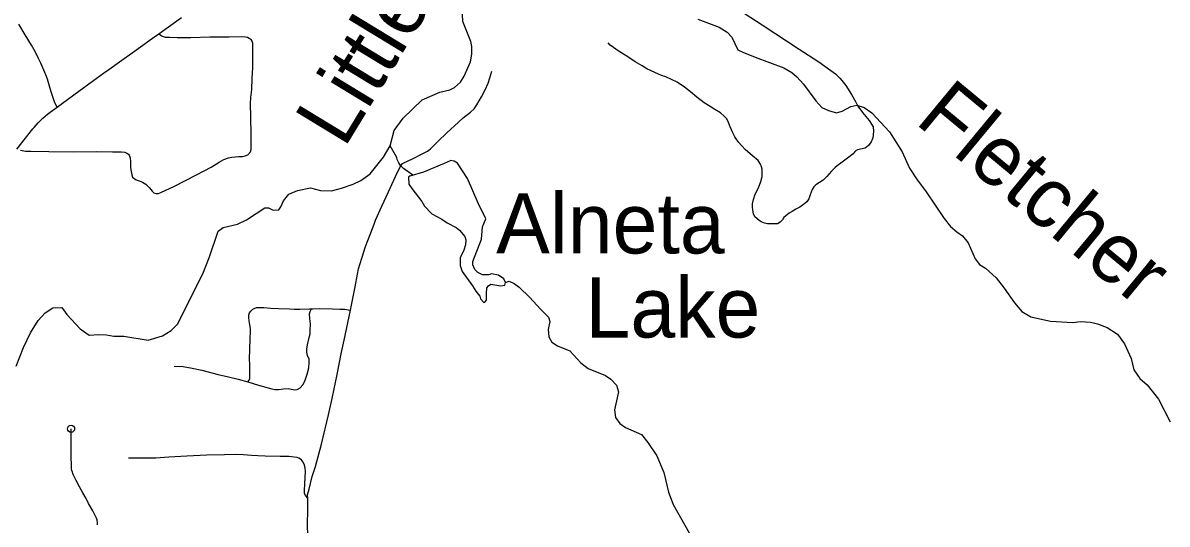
# Model space of a CAD drawing. Extents: x -19 to 366, y -4 to 359.
# Drawn here: x 139.407 to 140.926, y 193.112 to 193.777 of the extents above; entities that cross this region are included whole.
import ezdxf

# ---------------------------------------------------------------- set-up
doc = ezdxf.new("R2010")
doc.units = 0
for name, color, linetype in [('R_ROW', 7, 'Continuous'), ('R_ROW Annot', 7, 'Continuous'), ('R_Temp Easement', 7, 'Continuous'), ('Sheet Fence', 7, 'Continuous')]:
    doc.layers.add(name, color=color, linetype=linetype)

msp = doc.modelspace()

# ---------------------------------------------------------------- linework, layer by layer
at = {"layer": 'R_ROW'}
for points in [[(139.5877, 193.7626), (139.5975, 193.7697), (139.6178, 193.7843)], [(140.3569, 193.7949), (140.3883, 193.7743), (140.4375, 193.7422), (140.4635, 193.7253), (140.4797, 193.7138), (140.4856, 193.7096), (140.4916, 193.7038), (140.4944, 193.7004), (140.4995, 193.6941), (140.5071, 193.6818), (140.5128, 193.672), (140.5155, 193.6663), (140.5218, 193.658), (140.5304, 193.6474), (140.5358, 193.6392), (140.5364, 193.6327), (140.5353, 193.6246), (140.5331, 193.6192)], [(139.4529, 193.6652), (139.4498, 193.6708), (139.4456, 193.684), (139.4438, 193.6901), (139.4419, 193.6962), (139.4399, 193.7022), (139.4377, 193.7082), (139.4365, 193.7113), (139.4339, 193.7175), (139.4312, 193.7236), (139.4283, 193.7296), (139.4253, 193.7356), (139.4222, 193.7415), (139.419, 193.7473), (139.4106, 193.7614), (139.4022, 193.7753)], [(139.5146, 193.7102), (139.5213, 193.715), (139.5358, 193.7255), (139.5555, 193.7396), (139.5795, 193.7567), (139.5877, 193.7626)], [(139.7098, 193.6781), (139.7111, 193.6887), (139.7118, 193.7032), (139.7126, 193.7177), (139.7126, 193.7351), (139.7125, 193.7502), (139.7117, 193.7528), (139.7102, 193.755), (139.7079, 193.7565), (139.7056, 193.7577), (139.7027, 193.7583), (139.6979, 193.7586), (139.6814, 193.7582), (139.6554, 193.758), (139.6303, 193.7573), (139.6122, 193.7574), (139.6019, 193.7575), (139.5968, 193.7577), (139.5916, 193.7593), (139.5877, 193.7626)], [(139.4529, 193.6652), (139.4598, 193.6703), (139.4819, 193.6865), (139.5, 193.6996), (139.5146, 193.7102)], [(139.8423, 193.3957), (139.8483, 193.4266), (139.8513, 193.4436), (139.853, 193.4504), (139.8571, 193.4649), (139.8619, 193.4801), (139.8651, 193.4883), (139.8692, 193.4982), (139.8735, 193.51), (139.8754, 193.5152), (139.8838, 193.5337), (139.8926, 193.5526), (139.9043, 193.5781), (139.909, 193.5872), (139.9112, 193.5902), (139.9137, 193.5916), (139.9178, 193.5934), (139.9261, 193.5974), (139.9364, 193.6026), (139.9445, 193.6067), (139.9482, 193.61), (139.9583, 193.6196), (139.9702, 193.631), (139.9857, 193.6453), (139.9919, 193.6512), (140.0013, 193.6585), (140.0063, 193.6628), (140.0098, 193.6682), (140.016, 193.679), (140.0208, 193.6883), (140.0249, 193.6972), (140.0272, 193.7042), (140.0297, 193.7128)], [(139.3994, 193.6096), (139.4208, 193.6364), (139.4224, 193.6383), (139.4251, 193.6415), (139.4279, 193.6446), (139.4308, 193.6476), (139.4339, 193.6505), (139.437, 193.6532), (139.4402, 193.6559), (139.4435, 193.6584), (139.4529, 193.6652)], [(139.8179, 193.2783), (139.8245, 193.3103), (139.83, 193.3377), (139.835, 193.3621), (139.8423, 193.3957)], [(139.7854, 193.1463), (139.7853, 193.1507), (139.7872, 193.1581), (139.7915, 193.175), (139.7959, 193.1882), (139.8036, 193.2178), (139.8129, 193.2567), (139.8179, 193.2783)], [(139.5064, 193.1108), (139.5065, 193.1139), (139.5061, 193.117), (139.5052, 193.1196), (139.5001, 193.1294), (139.4945, 193.1393), (139.4912, 193.1458), (139.4871, 193.1534), (139.4824, 193.1614), (139.4781, 193.1697), (139.4746, 193.1768), (139.4738, 193.1788), (139.4731, 193.1809), (139.4725, 193.183), (139.4721, 193.1852), (139.4719, 193.1874), (139.4718, 193.1896), (139.4716, 193.2015), (139.4716, 193.2133), (139.4716, 193.2223), (139.4716, 193.2264), (139.4716, 193.23), (139.4714, 193.2383)], [(139.7854, 193.1463), (139.7825, 193.1498), (139.7812, 193.1527), (139.7811, 193.1561), (139.7814, 193.1657), (139.7823, 193.1811), (139.7819, 193.1864), (139.7808, 193.1912), (139.7791, 193.1946), (139.7771, 193.197), (139.7738, 193.1991), (139.7714, 193.2), (139.7674, 193.2007), (139.7602, 193.2014), (139.749, 193.2014), (139.729, 193.2019), (139.7193, 193.2023), (139.7109, 193.2029), (139.7, 193.2038), (139.6899, 193.204), (139.675, 193.2036), (139.6516, 193.2031), (139.625, 193.202), (139.6013, 193.2006), (139.5838, 193.1994), (139.5749, 193.1992), (139.5686, 193.1992), (139.5594, 193.1995), (139.5476, 193.1994)], [(139.7854, 193.0942), (139.7852, 193.1136), (139.7854, 193.1286), (139.7854, 193.1463)]]:
    msp.add_lwpolyline(points, dxfattribs=at)
msp.add_circle((139.4714, 193.2383), 0.00473, dxfattribs=at)
at = {"layer": 'R_ROW Annot'}
for points in [[(140.3462, 193.639), (140.3438, 193.6449), (140.3414, 193.6495), (140.3381, 193.6533), (140.3331, 193.6575), (140.3256, 193.6622), (140.3194, 193.666), (140.3116, 193.6711), (140.3019, 193.6786), (140.2935, 193.6855), (140.2853, 193.6919), (140.2756, 193.6985), (140.2682, 193.7021), (140.2605, 193.7054), (140.2547, 193.7074), (140.2459, 193.7113), (140.2354, 193.7162), (140.2291, 193.7201), (140.22, 193.7253), (140.21, 193.7319), (140.1988, 193.7391), (140.1866, 193.7476), (140.1839, 193.7506)], [(139.4044, 193.6082), (139.411, 193.607), (139.4181, 193.607), (139.4418, 193.6063), (139.4749, 193.6061), (139.5046, 193.6062), (139.5264, 193.6061), (139.5385, 193.6059), (139.5427, 193.6053), (139.5452, 193.6043), (139.5475, 193.6026), (139.5489, 193.6006), (139.5497, 193.5978), (139.5504, 193.5925), (139.5502, 193.5862), (139.5506, 193.5819), (139.5519, 193.5753), (139.5529, 193.5721), (139.5577, 193.5688), (139.5619, 193.5676), (139.5663, 193.5658), (139.5708, 193.5628), (139.5755, 193.5583), (139.5789, 193.5535), (139.5812, 193.5513), (139.5842, 193.5505), (139.5872, 193.5506), (139.5915, 193.5525), (139.6076, 193.5601), (139.6378, 193.5753), (139.6575, 193.5857), (139.6678, 193.5922), (139.6739, 193.5957), (139.6804, 193.5978), (139.6845, 193.5988), (139.6891, 193.5994), (139.6937, 193.5996), (139.699, 193.5996), (139.7025, 193.6005), (139.706, 193.6021), (139.7094, 193.6059), (139.7104, 193.6089), (139.7104, 193.6136), (139.7104, 193.6293), (139.7098, 193.6519), (139.7096, 193.6701), (139.7098, 193.6781)], [(140.5331, 193.6192), (140.5298, 193.6141), (140.5251, 193.6107), (140.5152, 193.6085), (140.512, 193.6066), (140.5091, 193.6033), (140.5017, 193.5973), (140.4929, 193.591), (140.4879, 193.5872), (140.4853, 193.5849), (140.4805, 193.5801), (140.4741, 193.573), (140.4695, 193.5685), (140.4647, 193.5653), (140.4598, 193.5621), (140.4569, 193.5596), (140.4549, 193.5557), (140.4523, 193.5487), (140.4506, 193.5437), (140.4477, 193.5397), (140.4434, 193.5358), (140.4386, 193.5324), (140.4333, 193.5296), (140.4282, 193.5266), (140.4242, 193.5243), (140.4199, 193.5208), (140.4174, 193.5186), (140.4155, 193.5158), (140.4122, 193.5127), (140.4088, 193.5105), (140.4006, 193.5105), (140.3955, 193.5105), (140.3915, 193.5112), (140.3873, 193.5129), (140.3843, 193.5147), (140.3789, 193.5197), (140.3768, 193.5238), (140.376, 193.5284), (140.3756, 193.5327), (140.3755, 193.5369), (140.3768, 193.5426), (140.3793, 193.5498), (140.3834, 193.5579), (140.3869, 193.5664), (140.3887, 193.573), (140.3887, 193.5788), (140.3887, 193.5827), (140.3877, 193.5861), (140.3862, 193.5896), (140.383, 193.5942), (140.3756, 193.6005), (140.3657, 193.6092), (140.361, 193.6143), (140.3576, 193.6184), (140.3549, 193.6219), (140.3521, 193.6256), (140.3494, 193.6311), (140.3462, 193.639)], [(139.7061, 193.3005), (139.7077, 193.3028), (139.7085, 193.3052), (139.7086, 193.3098), (139.7084, 193.3225), (139.7082, 193.3322), (139.7088, 193.3421), (139.7092, 193.3593), (139.7095, 193.3656), (139.7093, 193.3714), (139.7087, 193.3763), (139.7078, 193.3817), (139.7071, 193.386), (139.7072, 193.3893), (139.7081, 193.3923), (139.7098, 193.3946), (139.7125, 193.3971), (139.7143, 193.3981), (139.7175, 193.3992), (139.7208, 193.3994), (139.7272, 193.3992), (139.7365, 193.3985), (139.7465, 193.3981), (139.7613, 193.3973), (139.7675, 193.3969), (139.7748, 193.397), (139.7878, 193.3974), (139.7904, 193.3976)], [(139.7061, 193.3005), (139.72, 193.2961), (139.7377, 193.2915), (139.7416, 193.2904), (139.7467, 193.2906), (139.7535, 193.2915), (139.7596, 193.2917), (139.7683, 193.2901), (139.7713, 193.2904), (139.7752, 193.2925), (139.7789, 193.2965), (139.7814, 193.3013), (139.7848, 193.311), (139.7871, 193.3191), (139.7873, 193.3265), (139.7872, 193.3307), (139.7853, 193.3355), (139.7841, 193.3399), (139.7843, 193.344), (139.7853, 193.3498), (139.7875, 193.3593), (139.7885, 193.3642), (139.7887, 193.3688), (139.7892, 193.3774), (139.7881, 193.3845), (139.7879, 193.3907), (139.7885, 193.3941), (139.7904, 193.3976)], [(139.7904, 193.3976), (139.7924, 193.3977), (139.8014, 193.3979), (139.8183, 193.3976), (139.8282, 193.397), (139.8346, 193.3969), (139.8393, 193.396), (139.8423, 193.3957)], [(139.6081, 193.3212), (139.6201, 193.3209), (139.6322, 193.3187), (139.6449, 193.3162), (139.6665, 193.3104), (139.6802, 193.3073), (139.693, 193.3043), (139.7061, 193.3005)]]:
    msp.add_lwpolyline(points, dxfattribs=at)
at = {"layer": 'R_Temp Easement'}
for points in [[(139.9371, 193.6748), (139.9607, 193.6851), (139.9742, 193.6884), (139.9802, 193.6915), (139.988, 193.6985), (139.9932, 193.7065), (140.0015, 193.7253), (140.0033, 193.7355), (140.0031, 193.7458), (140.0018, 193.7522), (139.9911, 193.7788), (139.9905, 193.7979), (139.9934, 193.8033), (140.0093, 193.8218), (140.0156, 193.8314), (140.0348, 193.8753), (140.0438, 193.904), (140.0471, 193.9275), (140.0457, 193.9427), (140.0402, 193.9615)], [(140.303, 193.7819), (140.3314, 193.7714), (140.342, 193.7646), (140.3481, 193.7582), (140.3561, 193.7415), (140.3629, 193.7381), (140.3792, 193.7317), (140.4171, 193.7175), (140.4277, 193.7111), (140.4345, 193.7054), (140.4433, 193.6959), (140.4596, 193.6736), (140.4676, 193.6649), (140.4763, 193.6608), (140.4873, 193.6578), (140.4948, 193.6597), (140.5061, 193.6662), (140.5141, 193.6678), (140.5239, 193.6648), (140.5338, 193.6576), (140.5573, 193.6326), (140.5741, 193.6058), (140.584, 193.5842), (140.5931, 193.5702), (140.6061, 193.5528), (140.63, 193.5172), (140.6384, 193.5066), (140.6468, 193.4995), (140.6543, 193.4945), (140.6619, 193.4851), (140.6711, 193.4639), (140.6768, 193.4563), (140.6848, 193.4514), (140.6992, 193.4386), (140.7098, 193.425), (140.7232, 193.4053), (140.733, 193.3939), (140.7448, 193.3868), (140.7713, 193.3812), (140.8008, 193.3794), (140.811, 193.3806), (140.8242, 193.3799), (140.8333, 193.3776), (140.8462, 193.3727), (140.8602, 193.3641), (140.8693, 193.3512), (140.8781, 193.3315), (140.8816, 193.3167), (140.8896, 193.305), (140.8994, 193.2967), (140.9143, 193.2774), (140.9299, 193.2475)], [(139.3984, 193.3215), (139.4081, 193.3463), (139.4176, 193.3658), (139.4279, 193.3819), (139.4372, 193.3923), (139.4473, 193.399), (139.459, 193.3992), (139.4656, 193.3898), (139.4833, 193.3711), (139.4955, 193.3626), (139.5084, 193.3636), (139.5186, 193.363), (139.528, 193.3613), (139.5416, 193.3611), (139.5735, 193.356), (139.5927, 193.3616), (139.6042, 193.3686), (139.6128, 193.3771), (139.6464, 193.4441), (139.655, 193.4666), (139.6665, 193.5006), (139.6733, 193.5053), (139.6921, 193.5098), (139.7044, 193.5157), (139.7283, 193.5316), (139.7333, 193.5317), (139.7397, 193.5284), (139.7469, 193.5289), (139.7499, 193.5328), (139.7531, 193.5408), (139.7605, 193.5496), (139.7718, 193.5544), (139.7891, 193.5581), (139.8024, 193.5545), (139.8168, 193.554), (139.8303, 193.5577), (139.8457, 193.5632), (139.8558, 193.568), (139.8681, 193.5769), (139.8862, 193.5988), (139.8947, 193.6138), (139.9, 193.634), (139.9122, 193.6505), (139.9371, 193.6748)], [(139.9248, 193.5751), (139.9127, 193.5839), (139.9086, 193.5878), (139.9063, 193.5911), (139.9043, 193.5958), (139.9037, 193.5985), (139.8947, 193.6138)], [(139.9212, 193.5741), (139.9193, 193.5722), (139.9197, 193.5631), (139.9235, 193.5574), (139.9369, 193.54), (139.9403, 193.5339), (139.9502, 193.5234), (139.9634, 193.5166), (139.9706, 193.5117), (139.9824, 193.5056), (139.9869, 193.5019), (139.9938, 193.4935), (139.9953, 193.489), (139.995, 193.4825), (139.9927, 193.4753), (139.9878, 193.4651), (139.9879, 193.4552), (139.9902, 193.4469), (140.0043, 193.428), (140.0084, 193.4208), (140.0138, 193.4143), (140.0149, 193.4109), (140.0191, 193.406), (140.0206, 193.4064), (140.0225, 193.4091), (140.0228, 193.4174), (140.0232, 193.4254), (140.0251, 193.428), (140.0284, 193.4303), (140.0417, 193.4281), (140.047, 193.4289), (140.0477, 193.4323), (140.0458, 193.4372), (140.0386, 193.4421), (140.0291, 193.444), (140.0257, 193.4428), (140.0174, 193.4428), (140.011, 193.4458), (140.0072, 193.4496), (140.0045, 193.4557), (140.0045, 193.4602), (140.0161, 193.4898), (140.0175, 193.5062), (140.0217, 193.5168), (140.0114, 193.5376), (139.9976, 193.5706), (139.9843, 193.591)], [(139.9212, 193.5741), (139.9397, 193.5795), (139.9669, 193.5909), (139.9748, 193.5944)], [(139.9843, 193.591), (139.9797, 193.5936), (139.9748, 193.5944)], [(140.0477, 193.4323), (140.0526, 193.4342), (140.0594, 193.4312), (140.0659, 193.4263), (140.0803, 193.4127), (140.0944, 193.3972), (140.105, 193.3866), (140.1065, 193.3805), (140.1043, 193.3699), (140.1055, 193.3604), (140.1093, 193.3532), (140.1169, 193.3483), (140.1332, 193.3419), (140.148, 193.3257), (140.1575, 193.3181), (140.1806, 193.3091), (140.1878, 193.3042), (140.195, 193.2963), (140.1977, 193.2872), (140.1925, 193.2636), (140.1937, 193.2534), (140.1998, 193.2455), (140.2073, 193.2402), (140.2282, 193.2308), (140.2369, 193.2202), (140.2487, 193.2024), (140.2579, 193.1804), (140.264, 193.1543), (140.2702, 193.1376), (140.2915, 193.1001)]]:
    msp.add_lwpolyline(points, dxfattribs=at)
at = {"layer": 'Sheet Fence'}
for points in [[(146.7783, 1.697), (146.5788, 10.3131), (146.3785, 18.9294), (146.1776, 27.5458), (145.9759, 36.1624), (145.7736, 44.7791), (145.5705, 53.396), (145.3668, 62.013), (145.1624, 70.6301), (144.9572, 79.2474), (144.7514, 87.8648), (144.5449, 96.4823), (144.3377, 105.1), (144.1299, 113.7179), (143.9213, 122.3359), (143.712, 130.954), (143.5021, 139.5723), (143.2915, 148.1907), (143.0802, 156.8092), (142.8682, 165.4279), (142.6555, 174.0468), (142.4422, 182.6658), (142.2282, 191.2849), (142.0135, 199.9042), (141.7981, 208.5236), (141.582, 217.1432), (141.3653, 225.7629), (141.1479, 234.3828), (140.9298, 243.0028), (140.711, 251.623), (140.4916, 260.2433), (140.2715, 268.8638), (140.0508, 277.4844), (139.8293, 286.1051), (139.6072, 294.726), (139.3845, 303.3471), (139.161, 311.9683), (138.937, 320.5896), (138.7122, 329.2111), (138.4868, 337.8328), (138.2607, 346.4546)], [(139.4406, 1.5315), (139.2511, 10.1473), (139.0608, 18.7633), (138.8699, 27.3793), (138.6784, 35.9956), (138.4861, 44.6119), (138.2932, 53.2285), (138.0997, 61.8451), (137.9055, 70.4619), (137.7106, 79.0789), (137.5151, 87.6959), (137.319, 96.3132), (137.1221, 104.9306), (136.9247, 113.5481), (136.7265, 122.1658), (136.5278, 130.7836), (136.3283, 139.4016), (136.1282, 148.0197), (135.9275, 156.6379), (135.7261, 165.2564), (135.5241, 173.8749), (135.3214, 182.4936), (135.1181, 191.1125), (134.9141, 199.7315), (134.7095, 208.3506), (134.5043, 216.9699), (134.2984, 225.5894), (134.0919, 234.209), (133.8847, 242.8288), (133.6769, 251.4487), (133.4685, 260.0687), (133.2594, 268.6889), (133.0497, 277.3093), (132.8393, 285.9298), (132.6283, 294.5504), (132.4167, 303.1713), (132.2044, 311.7922), (131.9916, 320.4133), (131.778, 329.0346), (131.5639, 337.656), (131.3491, 346.2776)], [(0, 189.5162), (7.1121, 189.5206), (14.2243, 189.5339), (21.3364, 189.556), (28.4484, 189.5869), (35.5605, 189.6267), (42.6725, 189.6754), (49.7844, 189.7329), (56.8962, 189.7992), (64.0079, 189.8744), (71.1196, 189.9584), (78.2311, 190.0512), (85.3425, 190.1529), (92.4538, 190.2635), (99.5649, 190.3829), (106.6759, 190.5111), (113.7867, 190.6482), (120.8974, 190.7941), (128.0078, 190.9489), (135.1181, 191.1125), (142.2282, 191.2849), (149.338, 191.4662), (156.4476, 191.6563), (163.5569, 191.8553), (170.666, 192.0631), (177.7749, 192.2798), (184.8835, 192.5053), (191.9917, 192.7396), (199.0997, 192.9828), (206.2074, 193.2348), (213.3147, 193.4956), (220.4218, 193.7653), (227.5285, 194.0438), (234.6348, 194.3312), (241.7408, 194.6274), (248.8464, 194.9324), (255.9516, 195.2463), (263.0564, 195.569), (270.1608, 195.9005), (277.2648, 196.2409), (284.3683, 196.5901), (291.4715, 196.9481), (298.5741, 197.315), (305.6763, 197.6907), (312.7781, 198.0753), (319.8793, 198.4686), (326.9801, 198.8708), (334.0804, 199.2818), (341.1801, 199.7017)]]:
    msp.add_spline(points, degree=3, dxfattribs=at)

# ---------------------------------------------------------------- texts
at = {"layer": 'R_Temp Easement'}
for s, rotation, p in [('Little', 58.6889, (139.8339, 193.6095)), ('Fletcher', 320.3547, (140.5897, 193.6448))]:
    msp.add_text(s, height=0.08, rotation=rotation, dxfattribs=at).set_placement(p)
for s, p in [('Alneta', (140.0354, 193.471)), ('Lake', (140.1541, 193.3594))]:
    msp.add_text(s, height=0.08, dxfattribs=at).set_placement(p)

doc.saveas('drawing.dxf')
